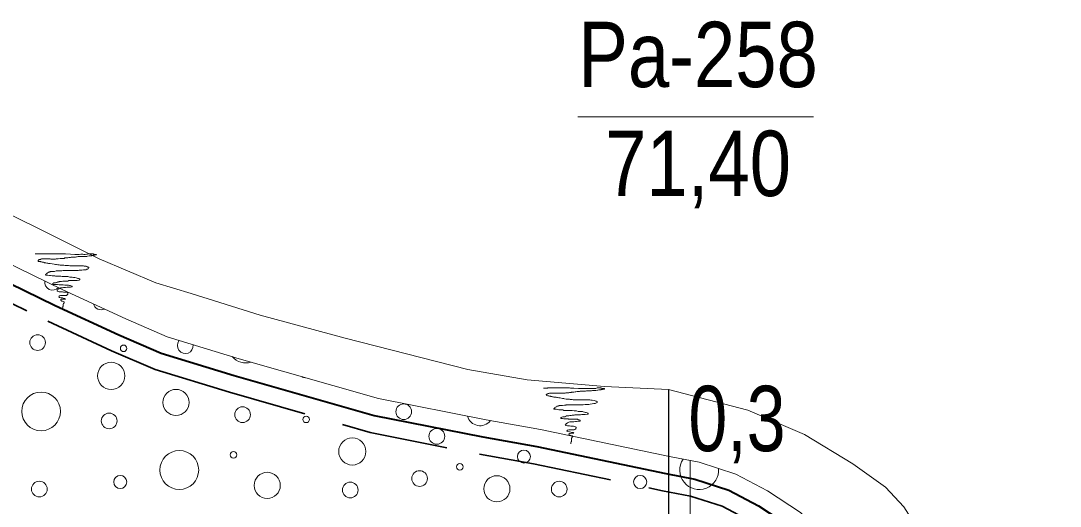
# Model space of a CAD drawing. Extents: x 640104 to 640970, y 6442278 to 6442689.
# Drawn here: x 640265.58 to 640313.3, y 6442429.39 to 6442451.67 of the extents above; entities that cross this region are included whole.
import ezdxf
from ezdxf.enums import TextEntityAlignment as Align

# ---------------------------------------------------------------- set-up
doc = ezdxf.new("R2010")
doc.units = 0
doc.header["$LTSCALE"] = 1.2
doc.linetypes.add('MEDIUM_DASHED', pattern=[4.5, 3, -1.5])
for name, color, linetype, lineweight in [('31', 7, 'Continuous', 13), ('32', 7, 'Continuous', 25), ('33', 7, 'Continuous', 13), ('35', 7, 'Continuous', 35), ('40', 7, 'Continuous', 13), ('41', 7, 'Continuous', 13)]:
    doc.layers.add(name, color=color, linetype=linetype, lineweight=lineweight)

msp = doc.modelspace()

# ---------------------------------------------------------------- linework, layer by layer
at = {"layer": '31'}
for points in [[(640262.65, 6442443.97), (640266.43, 6442442.13), (640269.19, 6442440.75), (640271.79, 6442439.65), (640273.4, 6442439.16), (640276.57, 6442438.16), (640280.48, 6442437.11), (640286.11, 6442435.67), (640288.83, 6442435.19), (640292.39, 6442434.88), (640295.32, 6442434.75), (640298.97, 6442433.8), (640301.57, 6442432.68), (640303.79, 6442431.34), (640305.28, 6442430.26), (640306.13, 6442429.37), (640307.82, 6442426.7), (640310.23, 6442423.67), (640311.17, 6442422.77), (640312.06, 6442422.33), (640313.81, 6442421.55)], [(640263.31, 6442441.37), (640267.52, 6442439.33), (640270.41, 6442437.99), (640272.31, 6442437.16), (640275.61, 6442436.16), (640282, 6442434.34), (640286.95, 6442433.35), (640289.44, 6442432.91), (640295.36, 6442431.67), (640296.73, 6442431.41), (640298.41, 6442430.87), (640299.86, 6442430.1), (640301.38, 6442429.11), (640303.59, 6442426.91), (640305.71, 6442424.37), (640308.28, 6442421.49), (640309.39, 6442420.52), (640311.41, 6442419.34), (640315.19, 6442417.97)]]:
    msp.add_lwpolyline(points, dxfattribs=at)
at = {"layer": '32', "lineweight": 13}
msp.add_line((640291.16, 6442447.27), (640301.98, 6442447.27), dxfattribs=at)
at = {"layer": '32'}
msp.add_line((640295.32, 6442434.75), (640295.32, 6442359.75), dxfattribs=at)
at = {"layer": '33'}
msp.add_lwpolyline([(640296.32, 6442389.75), (640296.32, 6442431.49), (640295.36, 6442431.67), (640295.32, 6442431.67), (640295.32, 6442389.82)], close=True, dxfattribs=at)
at = {"layer": '35', "lineweight": 40}
msp.add_lwpolyline([(640262.96, 6442440.65), (640267.17, 6442438.61), (640270.08, 6442437.26), (640272.03, 6442436.41), (640275.38, 6442435.39), (640281.81, 6442433.56), (640286.8, 6442432.57), (640289.28, 6442432.13), (640295.2, 6442430.89), (640296.53, 6442430.63), (640298.09, 6442430.13), (640299.45, 6442429.41), (640300.87, 6442428.48), (640303, 6442426.37), (640305.1, 6442423.85), (640307.71, 6442420.93), (640308.92, 6442419.86), (640311.07, 6442418.61), (640314.94, 6442417.21)], dxfattribs=at)
at = {"layer": '35', "linetype": 'MEDIUM_DASHED'}
msp.add_lwpolyline([(640262.62, 6442439.93), (640266.83, 6442437.89), (640269.75, 6442436.53), (640271.75, 6442435.66), (640275.16, 6442434.63), (640281.62, 6442432.78), (640286.65, 6442431.78), (640289.13, 6442431.34), (640295.05, 6442430.1), (640296.33, 6442429.86), (640297.78, 6442429.39), (640299.05, 6442428.72), (640300.37, 6442427.86), (640302.41, 6442425.83), (640304.5, 6442423.32), (640307.15, 6442420.36), (640308.45, 6442419.21), (640310.73, 6442417.89), (640314.69, 6442416.45)], dxfattribs=at)
at = {"layer": '40'}
for points in [[(640266.25, 6442440.97), (640266.29, 6442440.97), (640266.36, 6442440.97), (640266.43, 6442440.97), (640266.45, 6442440.97), (640266.52, 6442440.97), (640266.62, 6442440.97), (640266.84, 6442440.97), (640266.96, 6442440.97), (640266.98, 6442440.97), (640267.01, 6442440.97), (640267.06, 6442440.97), (640267.11, 6442440.97), (640267.18, 6442440.97), (640267.24, 6442440.97), (640267.28, 6442440.97), (640267.34, 6442440.97), (640267.38, 6442440.97), (640267.43, 6442440.97), (640267.49, 6442440.97), (640267.52, 6442440.97), (640267.57, 6442440.97), (640267.63, 6442440.97), (640267.86, 6442440.96), (640268.06, 6442440.95), (640268.13, 6442440.95), (640268.17, 6442440.95), (640268.19, 6442440.95), (640268.22, 6442440.95), (640268.27, 6442440.95), (640268.34, 6442440.96), (640268.37, 6442440.96), (640268.39, 6442440.96), (640268.41, 6442440.96), (640268.43, 6442440.96), (640268.48, 6442440.95), (640268.5, 6442440.95), (640268.54, 6442440.95), (640268.6, 6442440.96), (640268.64, 6442440.96), (640268.69, 6442440.97), (640268.71, 6442440.97), (640268.76, 6442440.97), (640268.78, 6442440.98), (640268.82, 6442440.98), (640268.85, 6442440.98), (640268.87, 6442440.97), (640268.9, 6442440.97), (640268.93, 6442440.96), (640268.95, 6442440.96)], [(640268.95, 6442440.96), (640268.98, 6442440.95), (640269.01, 6442440.95), (640269.04, 6442440.95), (640269.06, 6442440.93), (640269.04, 6442440.93), (640269.05, 6442440.93), (640269.02, 6442440.93), (640268.99, 6442440.92), (640268.95, 6442440.91), (640268.93, 6442440.91), (640268.9, 6442440.91), (640268.87, 6442440.9), (640268.85, 6442440.9), (640268.83, 6442440.89), (640268.79, 6442440.89), (640268.74, 6442440.88), (640268.72, 6442440.88), (640268.64, 6442440.87), (640268.61, 6442440.86), (640268.58, 6442440.86), (640268.55, 6442440.85), (640268.52, 6442440.85), (640268.5, 6442440.85), (640268.46, 6442440.85), (640268.43, 6442440.85), (640268.36, 6442440.85), (640268.32, 6442440.85), (640268.27, 6442440.85), (640268.22, 6442440.85), (640268.18, 6442440.84), (640268.14, 6442440.84), (640268.1, 6442440.83), (640268.06, 6442440.83), (640267.95, 6442440.83), (640267.93, 6442440.83), (640267.9, 6442440.82), (640267.86, 6442440.81), (640267.79, 6442440.81), (640267.74, 6442440.8), (640267.7, 6442440.8), (640267.64, 6442440.79), (640267.6, 6442440.79), (640267.57, 6442440.77), (640267.53, 6442440.77), (640267.51, 6442440.77), (640267.49, 6442440.77), (640267.45, 6442440.77), (640267.42, 6442440.76), (640267.39, 6442440.76), (640267.3, 6442440.75), (640267.27, 6442440.75)], [(640267.27, 6442440.75), (640267.25, 6442440.74), (640267.21, 6442440.74), (640267.18, 6442440.73), (640267.16, 6442440.73), (640267.14, 6442440.73), (640267.1, 6442440.73), (640267.07, 6442440.73), (640267.04, 6442440.73), (640266.99, 6442440.73), (640266.97, 6442440.73), (640266.93, 6442440.74), (640266.9, 6442440.74), (640266.88, 6442440.74), (640266.86, 6442440.74), (640266.82, 6442440.74), (640266.79, 6442440.74), (640266.74, 6442440.74), (640266.72, 6442440.74), (640266.7, 6442440.74), (640266.66, 6442440.74), (640266.63, 6442440.74), (640266.6, 6442440.74), (640266.58, 6442440.74), (640266.54, 6442440.74), (640266.51, 6442440.73), (640266.49, 6442440.72), (640266.46, 6442440.72), (640266.43, 6442440.71), (640266.42, 6442440.7), (640266.4, 6442440.69), (640266.38, 6442440.68), (640266.38, 6442440.65), (640266.38, 6442440.63), (640266.45, 6442440.62), (640266.49, 6442440.62), (640266.51, 6442440.61), (640266.54, 6442440.61), (640266.57, 6442440.6), (640266.58, 6442440.59), (640266.62, 6442440.59), (640266.66, 6442440.58), (640266.68, 6442440.57), (640266.73, 6442440.56), (640266.78, 6442440.55), (640266.82, 6442440.55), (640266.86, 6442440.54), (640266.89, 6442440.53), (640266.94, 6442440.53), (640267.02, 6442440.52)], [(640267.02, 6442440.52), (640267.11, 6442440.5), (640267.18, 6442440.49), (640267.22, 6442440.48), (640267.28, 6442440.47), (640267.34, 6442440.47), (640267.39, 6442440.46), (640267.43, 6442440.46), (640267.46, 6442440.45), (640267.52, 6442440.45), (640267.56, 6442440.45), (640267.62, 6442440.44), (640267.67, 6442440.44), (640267.72, 6442440.44), (640267.78, 6442440.44), (640267.84, 6442440.43), (640267.88, 6442440.43), (640267.9, 6442440.43), (640267.95, 6442440.43), (640268, 6442440.43), (640268.06, 6442440.43), (640268.12, 6442440.43), (640268.18, 6442440.43), (640268.22, 6442440.43), (640268.27, 6442440.43), (640268.3, 6442440.43), (640268.34, 6442440.43), (640268.38, 6442440.43), (640268.42, 6442440.42), (640268.46, 6442440.42), (640268.49, 6442440.41), (640268.58, 6442440.41), (640268.62, 6442440.39), (640268.66, 6442440.37), (640268.69, 6442440.37), (640268.71, 6442440.36), (640268.71, 6442440.33), (640268.7, 6442440.31), (640268.69, 6442440.3), (640268.67, 6442440.29), (640268.66, 6442440.28), (640268.62, 6442440.27), (640268.57, 6442440.25), (640268.47, 6442440.25), (640268.38, 6442440.23), (640268.34, 6442440.22), (640268.27, 6442440.22), (640268.22, 6442440.21), (640268.15, 6442440.21), (640268.06, 6442440.21), (640267.94, 6442440.21), (640267.82, 6442440.21)], [(640267.82, 6442440.21), (640267.77, 6442440.21), (640267.72, 6442440.21), (640267.66, 6442440.21), (640267.62, 6442440.21), (640267.58, 6442440.21), (640267.53, 6442440.21), (640267.47, 6442440.2), (640267.35, 6442440.2), (640267.3, 6442440.2), (640267.26, 6442440.19), (640267.21, 6442440.19), (640267.13, 6442440.17), (640267.04, 6442440.17), (640267.01, 6442440.17), (640266.97, 6442440.17), (640266.95, 6442440.16), (640266.93, 6442440.15), (640266.9, 6442440.15), (640266.88, 6442440.14), (640266.86, 6442440.13), (640266.84, 6442440.12), (640266.8, 6442440.09), (640266.78, 6442440.08), (640266.77, 6442440.06), (640266.74, 6442440.05), (640266.74, 6442440.04), (640266.72, 6442440.02), (640266.71, 6442440.01), (640266.73, 6442440), (640266.75, 6442440), (640266.79, 6442440), (640266.82, 6442440), (640266.9, 6442439.99), (640266.95, 6442439.98), (640267.02, 6442439.97), (640267.1, 6442439.97), (640267.14, 6442439.97), (640267.18, 6442439.95), (640267.22, 6442439.95), (640267.33, 6442439.95), (640267.42, 6442439.95), (640267.49, 6442439.94), (640267.56, 6442439.93), (640267.66, 6442439.93), (640267.75, 6442439.93), (640267.83, 6442439.9), (640267.89, 6442439.9), (640267.95, 6442439.9), (640268.01, 6442439.89)], [(640268.01, 6442439.89), (640268.04, 6442439.89), (640268.07, 6442439.89), (640268.13, 6442439.87), (640268.18, 6442439.86), (640268.21, 6442439.85), (640268.24, 6442439.84), (640268.28, 6442439.83), (640268.3, 6442439.82), (640268.3, 6442439.79), (640268.29, 6442439.78), (640268.27, 6442439.77), (640268.25, 6442439.77), (640268.17, 6442439.76), (640268.13, 6442439.76), (640268.1, 6442439.76), (640268.06, 6442439.76), (640268, 6442439.76), (640267.94, 6442439.75), (640267.91, 6442439.75), (640267.88, 6442439.75), (640267.79, 6442439.75), (640267.74, 6442439.73), (640267.72, 6442439.73), (640267.68, 6442439.73), (640267.66, 6442439.73), (640267.62, 6442439.73), (640267.56, 6442439.73), (640267.51, 6442439.72), (640267.46, 6442439.71), (640267.42, 6442439.7), (640267.39, 6442439.7), (640267.36, 6442439.7), (640267.34, 6442439.69), (640267.3, 6442439.69), (640267.29, 6442439.68), (640267.25, 6442439.67), (640267.23, 6442439.66), (640267.21, 6442439.66), (640267.18, 6442439.65), (640267.14, 6442439.65), (640267.1, 6442439.64), (640267.06, 6442439.62), (640267.05, 6442439.61), (640267.05, 6442439.57), (640267.07, 6442439.57), (640267.12, 6442439.57), (640267.18, 6442439.57), (640267.24, 6442439.57), (640267.27, 6442439.57), (640267.34, 6442439.56), (640267.38, 6442439.56)], [(640267.38, 6442439.56), (640267.39, 6442439.55), (640267.42, 6442439.55), (640267.46, 6442439.55), (640267.5, 6442439.55), (640267.53, 6442439.55), (640267.6, 6442439.54), (640267.66, 6442439.54), (640267.68, 6442439.54), (640267.71, 6442439.54), (640267.74, 6442439.54), (640267.78, 6442439.54), (640267.82, 6442439.53), (640267.85, 6442439.52), (640267.88, 6442439.51), (640267.91, 6442439.5), (640267.94, 6442439.49), (640267.94, 6442439.46), (640267.86, 6442439.45), (640267.75, 6442439.44), (640267.71, 6442439.44), (640267.64, 6442439.43), (640267.6, 6442439.43), (640267.55, 6442439.43), (640267.5, 6442439.42), (640267.46, 6442439.42), (640267.41, 6442439.41), (640267.35, 6442439.38), (640267.34, 6442439.37), (640267.3, 6442439.35), (640267.29, 6442439.33), (640267.27, 6442439.32), (640267.26, 6442439.29), (640267.25, 6442439.27), (640267.26, 6442439.26), (640267.3, 6442439.25), (640267.34, 6442439.24), (640267.43, 6442439.24), (640267.5, 6442439.23), (640267.54, 6442439.22), (640267.58, 6442439.21), (640267.62, 6442439.21), (640267.68, 6442439.21), (640267.74, 6442439.18), (640267.74, 6442439.15), (640267.74, 6442439.13), (640267.73, 6442439.11), (640267.68, 6442439.07), (640267.66, 6442439.06), (640267.62, 6442439.06), (640267.56, 6442439.06), (640267.5, 6442439.06), (640267.46, 6442439.06), (640267.4, 6442439.06), (640267.34, 6442439.05), (640267.34, 6442439.02), (640267.33, 6442439.01), (640267.34, 6442438.99), (640267.36, 6442438.98), (640267.44, 6442438.96), (640267.5, 6442438.95), (640267.53, 6442438.94), (640267.57, 6442438.93), (640267.61, 6442438.93), (640267.63, 6442438.91), (640267.62, 6442438.9), (640267.58, 6442438.9), (640267.53, 6442438.89), (640267.46, 6442438.89), (640267.44, 6442438.89), (640267.42, 6442438.88), (640267.42, 6442438.85), (640267.43, 6442438.83), (640267.45, 6442438.82), (640267.47, 6442438.81), (640267.5, 6442438.8), (640267.54, 6442438.79), (640267.58, 6442438.78), (640267.58, 6442438.75), (640267.57, 6442438.73), (640267.56, 6442438.71), (640267.54, 6442438.69), (640267.53, 6442438.67), (640267.53, 6442438.64), (640267.53, 6442438.61), (640267.53, 6442438.58), (640267.52, 6442438.56), (640267.52, 6442438.53), (640267.51, 6442438.51), (640267.5, 6442438.48), (640267.5, 6442438.45), (640267.5, 6442438.42), (640267.5, 6442438.41), (640267.5, 6442438.44)], [(640289.58, 6442434.81), (640289.62, 6442434.81), (640289.7, 6442434.81), (640289.77, 6442434.81), (640289.78, 6442434.82), (640289.86, 6442434.82), (640289.96, 6442434.82), (640290.18, 6442434.82), (640290.3, 6442434.82), (640290.32, 6442434.82), (640290.34, 6442434.82), (640290.39, 6442434.82), (640290.45, 6442434.82), (640290.52, 6442434.82), (640290.58, 6442434.82), (640290.62, 6442434.82), (640290.67, 6442434.82), (640290.72, 6442434.82), (640290.77, 6442434.82), (640290.82, 6442434.81), (640290.86, 6442434.81), (640290.9, 6442434.81), (640290.97, 6442434.81), (640291.19, 6442434.8), (640291.4, 6442434.79), (640291.46, 6442434.79), (640291.5, 6442434.79), (640291.53, 6442434.79), (640291.56, 6442434.79), (640291.61, 6442434.79), (640291.67, 6442434.8), (640291.7, 6442434.8), (640291.73, 6442434.8), (640291.74, 6442434.8), (640291.77, 6442434.8), (640291.82, 6442434.79), (640291.84, 6442434.79), (640291.87, 6442434.79), (640291.94, 6442434.8), (640291.98, 6442434.8), (640292.02, 6442434.81), (640292.05, 6442434.82), (640292.1, 6442434.82), (640292.12, 6442434.82), (640292.15, 6442434.82), (640292.18, 6442434.82), (640292.21, 6442434.82), (640292.23, 6442434.81), (640292.26, 6442434.8), (640292.29, 6442434.8)], [(640290.61, 6442434.59), (640290.58, 6442434.58), (640290.54, 6442434.58), (640290.52, 6442434.58), (640290.5, 6442434.58), (640290.47, 6442434.58), (640290.44, 6442434.58), (640290.41, 6442434.58), (640290.38, 6442434.58), (640290.33, 6442434.58), (640290.3, 6442434.58), (640290.26, 6442434.58), (640290.24, 6442434.58), (640290.22, 6442434.58), (640290.19, 6442434.58), (640290.16, 6442434.58), (640290.13, 6442434.58), (640290.08, 6442434.58), (640290.06, 6442434.58), (640290.03, 6442434.58), (640289.99, 6442434.58), (640289.97, 6442434.58), (640289.94, 6442434.58), (640289.91, 6442434.58), (640289.88, 6442434.58), (640289.85, 6442434.58), (640289.82, 6442434.56), (640289.79, 6442434.56), (640289.77, 6442434.55), (640289.75, 6442434.54), (640289.74, 6442434.54), (640289.72, 6442434.52), (640289.71, 6442434.5), (640289.72, 6442434.47), (640289.78, 6442434.46), (640289.82, 6442434.46), (640289.85, 6442434.45), (640289.88, 6442434.45), (640289.9, 6442434.44), (640289.92, 6442434.43), (640289.96, 6442434.43), (640289.99, 6442434.42), (640290.02, 6442434.42), (640290.06, 6442434.4), (640290.11, 6442434.39), (640290.16, 6442434.39), (640290.19, 6442434.38), (640290.22, 6442434.38), (640290.28, 6442434.37), (640290.35, 6442434.36)], [(640292.29, 6442434.8), (640292.32, 6442434.79), (640292.34, 6442434.79), (640292.38, 6442434.79), (640292.39, 6442434.78), (640292.38, 6442434.77), (640292.38, 6442434.78), (640292.36, 6442434.77), (640292.33, 6442434.76), (640292.29, 6442434.75), (640292.26, 6442434.75), (640292.23, 6442434.75), (640292.21, 6442434.74), (640292.18, 6442434.74), (640292.17, 6442434.73), (640292.13, 6442434.73), (640292.08, 6442434.72), (640292.06, 6442434.72), (640291.98, 6442434.71), (640291.94, 6442434.7), (640291.92, 6442434.7), (640291.89, 6442434.7), (640291.86, 6442434.7), (640291.83, 6442434.7), (640291.79, 6442434.69), (640291.77, 6442434.69), (640291.7, 6442434.69), (640291.66, 6442434.69), (640291.61, 6442434.69), (640291.55, 6442434.69), (640291.51, 6442434.68), (640291.48, 6442434.68), (640291.44, 6442434.67), (640291.4, 6442434.67), (640291.29, 6442434.67), (640291.26, 6442434.67), (640291.24, 6442434.66), (640291.19, 6442434.66), (640291.13, 6442434.65), (640291.07, 6442434.64), (640291.03, 6442434.64), (640290.98, 6442434.63), (640290.94, 6442434.63), (640290.9, 6442434.62), (640290.86, 6442434.62), (640290.85, 6442434.61), (640290.82, 6442434.61), (640290.78, 6442434.61), (640290.75, 6442434.6), (640290.73, 6442434.6), (640290.64, 6442434.59), (640290.61, 6442434.59)], [(640290.35, 6442434.36), (640290.45, 6442434.34), (640290.51, 6442434.33), (640290.55, 6442434.32), (640290.62, 6442434.31), (640290.68, 6442434.31), (640290.73, 6442434.3), (640290.77, 6442434.3), (640290.8, 6442434.29), (640290.86, 6442434.29), (640290.9, 6442434.29), (640290.95, 6442434.28), (640291.01, 6442434.28), (640291.06, 6442434.28), (640291.12, 6442434.28), (640291.18, 6442434.27), (640291.22, 6442434.27), (640291.24, 6442434.27), (640291.29, 6442434.27), (640291.34, 6442434.27), (640291.39, 6442434.27), (640291.46, 6442434.27), (640291.51, 6442434.27), (640291.55, 6442434.27), (640291.61, 6442434.27), (640291.63, 6442434.27), (640291.67, 6442434.27), (640291.71, 6442434.27), (640291.75, 6442434.26), (640291.79, 6442434.26), (640291.82, 6442434.26), (640291.91, 6442434.25), (640291.95, 6442434.23), (640291.99, 6442434.22), (640292.02, 6442434.21), (640292.05, 6442434.2), (640292.05, 6442434.18), (640292.04, 6442434.15), (640292.02, 6442434.14), (640292.01, 6442434.14), (640291.99, 6442434.12), (640291.96, 6442434.11), (640291.9, 6442434.1), (640291.81, 6442434.09), (640291.72, 6442434.07), (640291.67, 6442434.06), (640291.61, 6442434.06), (640291.55, 6442434.06), (640291.49, 6442434.06), (640291.4, 6442434.05), (640291.27, 6442434.05), (640291.16, 6442434.05)], [(640291.16, 6442434.05), (640291.1, 6442434.05), (640291.06, 6442434.05), (640291, 6442434.05), (640290.96, 6442434.05), (640290.92, 6442434.05), (640290.86, 6442434.05), (640290.81, 6442434.04), (640290.69, 6442434.04), (640290.63, 6442434.04), (640290.6, 6442434.03), (640290.54, 6442434.03), (640290.46, 6442434.02), (640290.38, 6442434.02), (640290.34, 6442434.01), (640290.3, 6442434.01), (640290.29, 6442434), (640290.26, 6442433.99), (640290.24, 6442433.99), (640290.22, 6442433.98), (640290.19, 6442433.98), (640290.18, 6442433.96), (640290.14, 6442433.94), (640290.11, 6442433.92), (640290.1, 6442433.9), (640290.08, 6442433.9), (640290.07, 6442433.88), (640290.06, 6442433.86), (640290.05, 6442433.85), (640290.06, 6442433.84), (640290.09, 6442433.84), (640290.13, 6442433.84), (640290.16, 6442433.84), (640290.23, 6442433.83), (640290.29, 6442433.82), (640290.35, 6442433.82), (640290.43, 6442433.81), (640290.47, 6442433.81), (640290.51, 6442433.79), (640290.55, 6442433.79), (640290.66, 6442433.79), (640290.75, 6442433.79), (640290.82, 6442433.78), (640290.9, 6442433.78), (640290.99, 6442433.77), (640291.09, 6442433.77), (640291.17, 6442433.74), (640291.22, 6442433.74), (640291.29, 6442433.74), (640291.34, 6442433.74)], [(640291.34, 6442433.74), (640291.38, 6442433.74), (640291.41, 6442433.73), (640291.46, 6442433.71), (640291.51, 6442433.7), (640291.54, 6442433.69), (640291.58, 6442433.68), (640291.62, 6442433.67), (640291.63, 6442433.66), (640291.64, 6442433.63), (640291.62, 6442433.62), (640291.61, 6442433.62), (640291.58, 6442433.61), (640291.5, 6442433.6), (640291.46, 6442433.6), (640291.44, 6442433.6), (640291.39, 6442433.6), (640291.34, 6442433.6), (640291.28, 6442433.59), (640291.25, 6442433.59), (640291.22, 6442433.59), (640291.13, 6442433.59), (640291.08, 6442433.58), (640291.06, 6442433.58), (640291.02, 6442433.58), (640290.99, 6442433.57), (640290.95, 6442433.57), (640290.9, 6442433.57), (640290.85, 6442433.56), (640290.79, 6442433.55), (640290.75, 6442433.54), (640290.73, 6442433.54), (640290.7, 6442433.54), (640290.67, 6442433.54), (640290.63, 6442433.54), (640290.62, 6442433.52), (640290.58, 6442433.51), (640290.57, 6442433.5), (640290.54, 6442433.5), (640290.51, 6442433.5), (640290.47, 6442433.49), (640290.43, 6442433.48), (640290.4, 6442433.46), (640290.38, 6442433.45), (640290.38, 6442433.42), (640290.41, 6442433.42), (640290.46, 6442433.42), (640290.52, 6442433.41), (640290.58, 6442433.41), (640290.61, 6442433.41), (640290.67, 6442433.4), (640290.71, 6442433.4)], [(640290.71, 6442433.4), (640290.73, 6442433.39), (640290.75, 6442433.39), (640290.79, 6442433.39), (640290.84, 6442433.39), (640290.86, 6442433.39), (640290.94, 6442433.38), (640290.99, 6442433.38), (640291.02, 6442433.38), (640291.05, 6442433.38), (640291.07, 6442433.38), (640291.11, 6442433.38), (640291.15, 6442433.38), (640291.18, 6442433.36), (640291.22, 6442433.35), (640291.25, 6442433.34), (640291.27, 6442433.34), (640291.27, 6442433.3), (640291.19, 6442433.29), (640291.09, 6442433.28), (640291.05, 6442433.28), (640290.98, 6442433.27), (640290.94, 6442433.27), (640290.89, 6442433.27), (640290.84, 6442433.26), (640290.79, 6442433.26), (640290.74, 6442433.25), (640290.69, 6442433.22), (640290.67, 6442433.21), (640290.64, 6442433.19), (640290.62, 6442433.18), (640290.61, 6442433.16), (640290.6, 6442433.14), (640290.58, 6442433.11), (640290.6, 6442433.1), (640290.63, 6442433.1), (640290.68, 6442433.08), (640290.77, 6442433.08), (640290.84, 6442433.07), (640290.88, 6442433.06), (640290.91, 6442433.06), (640290.96, 6442433.06), (640291.02, 6442433.05), (640291.08, 6442433.02), (640291.08, 6442432.99), (640291.07, 6442432.97), (640291.06, 6442432.95), (640291.02, 6442432.91), (640290.99, 6442432.9), (640290.95, 6442432.9), (640290.9, 6442432.9), (640290.84, 6442432.9), (640290.79, 6442432.9), (640290.74, 6442432.9), (640290.68, 6442432.89), (640290.67, 6442432.86), (640290.66, 6442432.85), (640290.67, 6442432.83), (640290.7, 6442432.82), (640290.78, 6442432.8), (640290.83, 6442432.79), (640290.86, 6442432.78), (640290.9, 6442432.78), (640290.94, 6442432.77), (640290.97, 6442432.75), (640290.95, 6442432.74), (640290.91, 6442432.74), (640290.86, 6442432.74), (640290.8, 6442432.73), (640290.78, 6442432.73), (640290.75, 6442432.72), (640290.75, 6442432.69), (640290.77, 6442432.67), (640290.78, 6442432.66), (640290.81, 6442432.65), (640290.84, 6442432.64), (640290.88, 6442432.63), (640290.91, 6442432.62), (640290.92, 6442432.59), (640290.9, 6442432.58), (640290.9, 6442432.55), (640290.88, 6442432.53), (640290.86, 6442432.51), (640290.86, 6442432.48), (640290.86, 6442432.45), (640290.86, 6442432.42), (640290.86, 6442432.4), (640290.86, 6442432.37), (640290.85, 6442432.35), (640290.84, 6442432.32), (640290.83, 6442432.3), (640290.83, 6442432.26), (640290.83, 6442432.26), (640290.83, 6442432.28)]]:
    msp.add_lwpolyline(points, dxfattribs=at)
at = {"layer": '41'}
for centre, radius in [((640266.357, 6442436.904), 0.36), ((640270.306, 6442436.639), 0.15), ((640269.737, 6442435.375), 0.624), ((640266.517, 6442433.743), 0.889), ((640272.709, 6442434.155), 0.6), ((640269.642, 6442433.307), 0.36), ((640275.766, 6442433.594), 0.36), ((640283.166, 6442433.731), 0.36), ((640278.682, 6442433.378), 0.15), ((640284.685, 6442432.599), 0.36), ((640280.804, 6442431.907), 0.624), ((640272.86, 6442431.053), 0.893), ((640275.346, 6442431.746), 0.15), ((640288.684, 6442431.668), 0.3), ((640285.738, 6442431.203), 0.15), ((640270.15, 6442430.504), 0.3), ((640276.897, 6442430.348), 0.6), ((640283.893, 6442430.662), 0.36), ((640287.442, 6442430.192), 0.6), ((640294.019, 6442430.504), 0.3), ((640266.435, 6442430.178), 0.36), ((640280.711, 6442430.136), 0.36), ((640290.304, 6442430.178), 0.36)]:
    msp.add_circle(centre, radius, dxfattribs=at)
for centre, radius, start, end in [((640267.041, 6442439.67), 0.36, 169.9511, 318.3429), ((640269.268, 6442438.767), 0.36, 194.3667, 295.7417), ((640273.137, 6442436.761), 0.36, 139.9134, 6.3698), ((640275.92, 6442436.8), 0.834, 220.6438, 286.8579), ((640278.665, 6442435.652), 0.36, 239.7463, 268.4577), ((640286.668, 6442433.687), 0.6, 195.7357, 322.1622), ((640296.729, 6442431.053), 0.893, 146.0372, 4.4227)]:
    msp.add_arc(centre, radius, start, end, dxfattribs=at)

# ---------------------------------------------------------------- texts
at = {"layer": '32'}
for s, width, p in [('Pa-258', 0.85, (640296.68, 6442448.63)), ('71,40', 0.85, (640296.68, 6442443.63)), ('0,3', 0.8, (640298.465, 6442431.92))]:
    msp.add_text(s, height=3, dxfattribs=dict(at, width=width)).set_placement(p, align=Align.CENTER)

doc.saveas('drawing.dxf')
